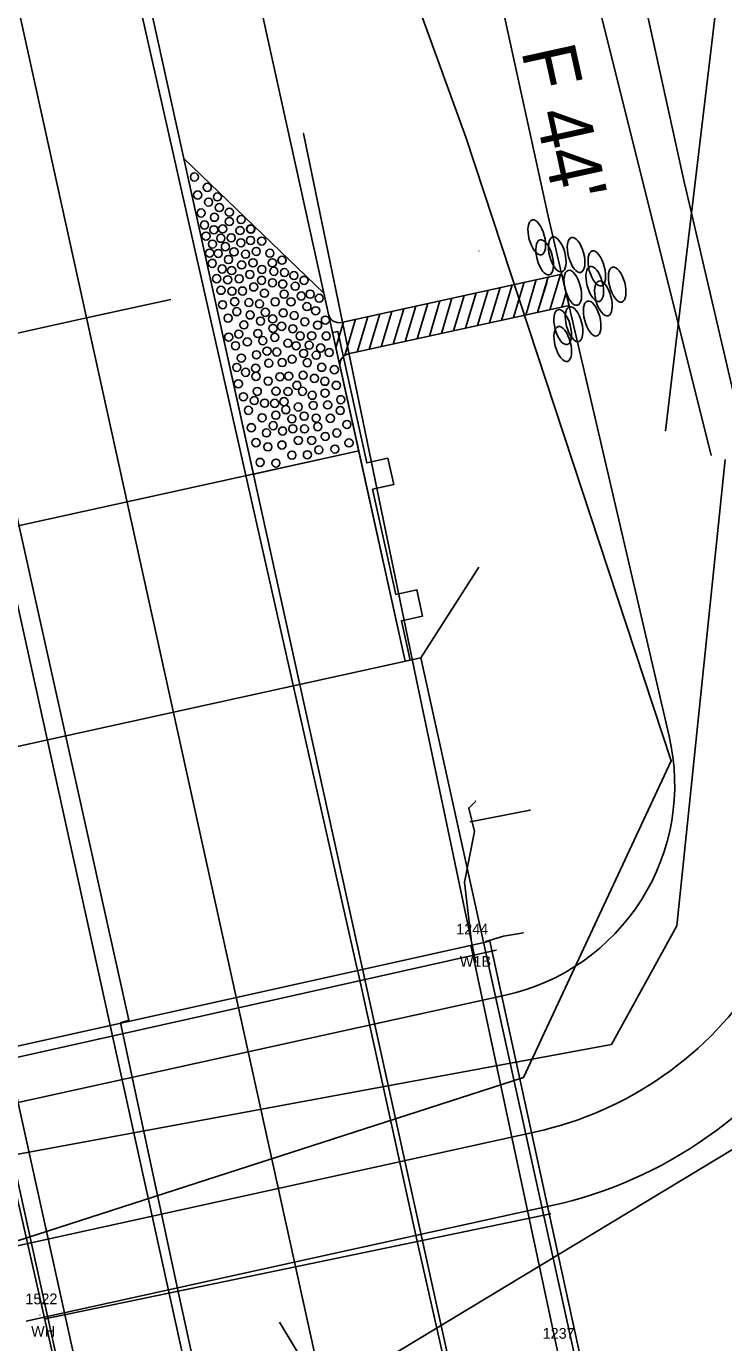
# Model space of a CAD drawing. Extents: x 2519952 to 2531965, y 848341 to 887632.
# Drawn here: x 2524242.1 to 2524306.9, y 857048.4 to 857170.6 of the extents above; entities that cross this region are included whole.
import ezdxf

# ---------------------------------------------------------------- set-up
doc = ezdxf.new("R2010")
doc.units = 0
for name, color, linetype in [('RD_EV_JW', 7, 'Continuous'), ('RD_EX_BldgApp', 7, 'Continuous'), ('RD_EX_BldgApp_txCode', 7, 'Continuous'), ('RD_EX_Bridge', 7, 'Continuous'), ('RD_EX_Conc', 7, 'Continuous'), ('RD_EX_DR_Pipe', 7, 'Continuous'), ('RD_EX_GuardRail', 7, 'Continuous'), ('RD_EX_H2O', 7, 'Continuous'), ('RD_EX_Misc', 7, 'Continuous'), ('RD_EX_Road', 7, 'Continuous'), ('RD_EX_VEG', 7, 'Continuous'), ('RD_HC_Cl', 7, 'Continuous'), ('RD_HC_Data_Tic', 7, 'Continuous'), ('RD_PD_BCA', 7, 'Continuous'), ('RD_PD_Bridge', 7, 'Continuous'), ('RD_PD_CstnLmt', 7, 'Continuous'), ('RD_PD_DR_ErosCtrl', 7, 'Continuous'), ('RD_PD_Final_TrvlWay', 7, 'Continuous'), ('RD_PD_GR', 7, 'Continuous'), ('RD_PD_PaveShd', 7, 'Continuous'), ('RD_PD_TX_CstnLmt', 7, 'Continuous'), ('RD_SMD_Locator', 7, 'Continuous')]:
    doc.layers.add(name, color=color, linetype=linetype)

# ---------------------------------------------------------------- blocks, each defined once
blk = doc.blocks.new('TBC1')
at = {"layer": 'RD_PD_GR'}
blk.add_lwpolyline([(12.5, 2.5), (15, 2.5), (15, 0.49), (25, 0.49), (25, 2.5), (27.5, 2.5), (27.5, 0.49), (31.25, 0.49), (31.25, 0), (0, 0), (0, 0.49), (12.5, 0.49)], close=True, dxfattribs=at)

msp = doc.modelspace()

# ---------------------------------------------------------------- linework, layer by layer
at = {"layer": 'RD_EV_JW'}
msp.add_lwpolyline([(2524241.25, 857057.8), (2524288.29, 857072.98), (2524302, 857102.41), (2524282.93, 857160.32), (2524257.89, 857229.33), (2524228.28, 857368.09), (2524210.76, 857440.65), (2524188.72, 857541.07), (2524178.8, 857585.79), (2524207.91, 857589.59), (2524237.38, 857595.52)], dxfattribs=at)
at = {"layer": 'RD_EX_BldgApp'}
for points in [[(2524299.52, 857011.21), (2524291.4, 857047.73), (2524283.39, 857085.27)], [(2524256.76, 857001.69), (2524248.36, 857039.08), (2524240.29, 857075.67)]]:
    msp.add_lwpolyline(points, dxfattribs=at)
at = {"layer": 'RD_EX_Bridge'}
for points in [[(2524288.28, 857086.43), (2524286.42, 857086.12), (2524284.79, 857085.63)], [(2524254.99, 857001.37), (2524301.28, 857011.6), (2524285.15, 857085.66), (2524238.23, 857075.21), (2524254.99, 857001.37)]]:
    msp.add_lwpolyline(points, dxfattribs=at)
at = {"layer": 'RD_EX_Conc'}
msp.add_lwpolyline([(2524283.42, 857085.84), (2524282.82, 857091.13), (2524283.73, 857095.82), (2524283.2, 857098.01), (2524283.85, 857098.66)], dxfattribs=at)
at = {"layer": 'RD_EX_DR_Pipe'}
msp.add_line((2524283.35, 857096.74), (2524288.89, 857097.83), dxfattribs=at)
at = {"layer": 'RD_EX_GuardRail'}
msp.add_lwpolyline([(2524283.87, 857083.68), (2524278.32, 857110.03), (2524267.88, 857160.66)], dxfattribs=at)
at = {"layer": 'RD_EX_H2O'}
msp.add_lwpolyline([(2524218.99, 857071.27), (2524223.78, 857062.61), (2524296.44, 857076.06), (2524302.51, 857087.07), (2524307.01, 857130.38)], dxfattribs=at)
at = {"layer": 'RD_EX_Misc'}
for p, q in [((2524238.53, 857074.24), (2524285.74, 857084.83)), ((2524290.8, 857060.34), (2524243.91, 857050.57))]:
    msp.add_line(p, q, dxfattribs=at)
msp.add_lwpolyline([(2524546.39, 857089.12), (2524517.38, 857137.92), (2524538.03, 857176.84), (2524519.61, 857206.94), (2524513, 857216.34), (2524463.61, 857251.75), (2524420.32, 857237.04), (2524384.22, 857230.02), (2524354.94, 857196.44), (2524330.04, 857206.28), (2524307.73, 857185.7), (2524301.47, 857133.05)], dxfattribs=at)
at = {"layer": 'RD_EX_Road'}
for p, q in [((2524272.86, 857083.08), (2524251.32, 857178.56)), ((2524251.66, 857078.33), (2524230.4, 857173.95)), ((2524272.98, 857082.6), (2524272.86, 857083.08)), ((2524278.38, 857057.92), (2524272.98, 857082.6)), ((2524250.88, 857078.06), (2524251.66, 857078.33)), ((2524256.26, 857052.98), (2524250.88, 857078.06)), ((2524283.87, 857033.71), (2524278.38, 857057.92)), ((2524261.6, 857028.54), (2524256.26, 857052.98))]:
    msp.add_line(p, q, dxfattribs=at)
at = {"layer": 'RD_EX_VEG'}
msp.add_lwpolyline([(2524305.71, 857130.78), (2524291.95, 857185.88), (2524213.1, 857577.99), (2524167.19, 857800.01)], dxfattribs=at)
at = {"layer": 'RD_HC_Cl'}
for p, q in [((2524121.25, 857717.97), (2524677.84, 855190.33)), ((2524152.13, 856972.4), (2524317.26, 857072.09))]:
    msp.add_line(p, q, dxfattribs=at)
at = {"layer": 'RD_HC_Data_Tic'}
for p, q in [((2524247.74, 857143.53), (2524255.55, 857145.25)), ((2524247.74, 857143.53), (2524239.93, 857141.81)), ((2524269.78, 857043.43), (2524265.64, 857050.27))]:
    msp.add_line(p, q, dxfattribs=at)
at = {"layer": 'RD_PD_BCA'}
msp.add_lwpolyline([(2524242.14, 857050.37), (2524290.92, 857061.11)], dxfattribs=at)
msp.add_arc((2524282.32, 857100.17), 40, 282.4185, 13.0724, dxfattribs=at)
at = {"layer": 'RD_PD_Bridge'}
for p, q in [((2524230.02, 857121.71), (2524272.99, 857131.17)), ((2524277.29, 857111.64), (2524272.99, 857131.17)), ((2524278.76, 857111.96), (2524284.14, 857120.39))]:
    msp.add_line(p, q, dxfattribs=at)
for points in [[(2524278.76, 857111.96), (2524232.86, 857101.86)], [(2524306.71, 856985.01), (2524278.76, 857111.96)], [(2524232.86, 857101.86), (2524260.81, 856974.9)]]:
    msp.add_lwpolyline(points, dxfattribs=at)
at = {"layer": 'RD_PD_CstnLmt'}
for p, q in [((2524269.22, 857250.66), (2524290.59, 857152.97)), ((2524290.59, 857152.97), (2524301.8, 857104.7))]:
    msp.add_line(p, q, dxfattribs=at)
msp.add_lwpolyline([(2524237.84, 857069.9), (2524286.62, 857080.64)], dxfattribs=at)
msp.add_arc((2524282.32, 857100.17), 20, 282.4185, 13.0724, dxfattribs=at)
at = {"layer": 'RD_PD_DR_ErosCtrl'}
for p, q in [((2524281.92, 857253.43), (2524303.29, 857155.74)), ((2524303.26, 857155.91), (2524314.47, 857107.64))]:
    msp.add_line(p, q, dxfattribs=at)
msp.add_lwpolyline([(2524240.63, 857057.2), (2524289.42, 857067.94)], dxfattribs=at)
msp.add_arc((2524282.32, 857100.17), 33, 282.4185, 13.0724, dxfattribs=at)
at = {"layer": 'RD_PD_Final_TrvlWay'}
for p, q in [((2524221.83, 857317.02), (2524496.02, 856071.85)), ((2524198.39, 857311.86), (2524472.58, 856066.69))]:
    msp.add_line(p, q, dxfattribs=at)
at = {"layer": 'RD_PD_GR'}
msp.add_line((2524222.18, 857361.9), (2524270.57, 857142.16), dxfattribs=at)
at = {"layer": 'RD_PD_PaveShd'}
for p, q in [((2524256.77, 857158.32), (2524269.76, 857145.82)), ((2524263.22, 857129.02), (2524256.77, 857158.32)), ((2524271.39, 857143.11), (2524291.84, 857147.6)), ((2524289.6, 857144.04), (2524290.59, 857147.33)), ((2524290.72, 857144.28), (2524291.71, 857147.57)), ((2524290.72, 857144.28), (2524291.71, 857147.57)), ((2524291.84, 857147.6), (2524292.52, 857144.68)), ((2524284.02, 857142.81), (2524285, 857146.1)), ((2524284.02, 857142.81), (2524285, 857146.1)), ((2524285.14, 857143.06), (2524286.12, 857146.34)), ((2524285.14, 857143.06), (2524286.12, 857146.34)), ((2524286.25, 857143.3), (2524287.24, 857146.59)), ((2524286.25, 857143.3), (2524287.12, 857146.18)), ((2524287.37, 857143.55), (2524288.35, 857146.83)), ((2524287.37, 857143.55), (2524288.35, 857146.83)), ((2524288.49, 857143.79), (2524289.47, 857147.08)), ((2524288.49, 857143.79), (2524289.47, 857147.08)), ((2524289.6, 857144.04), (2524290.47, 857146.92)), ((2524270.41, 857142.89), (2524269.76, 857145.82)), ((2524278.43, 857141.58), (2524279.42, 857144.87)), ((2524278.43, 857141.58), (2524279.42, 857144.87)), ((2524279.55, 857141.83), (2524280.53, 857145.12)), ((2524279.55, 857141.83), (2524280.53, 857145.12)), ((2524280.67, 857142.07), (2524281.65, 857145.36)), ((2524280.67, 857142.07), (2524281.65, 857145.36)), ((2524281.78, 857142.32), (2524282.77, 857145.61)), ((2524281.78, 857142.32), (2524282.77, 857145.61)), ((2524282.9, 857142.56), (2524283.88, 857145.85)), ((2524282.9, 857142.56), (2524283.88, 857145.85)), ((2524291.84, 857144.53), (2524292.24, 857145.87)), ((2524291.84, 857144.53), (2524292.24, 857145.87)), ((2524292.52, 857144.68), (2524272.03, 857140.18)), ((2524272.84, 857140.36), (2524273.83, 857143.64)), ((2524272.84, 857140.36), (2524273.83, 857143.64)), ((2524273.96, 857140.6), (2524274.95, 857143.89)), ((2524273.96, 857140.6), (2524274.95, 857143.89)), ((2524275.08, 857140.85), (2524276.06, 857144.13)), ((2524275.08, 857140.85), (2524276.06, 857144.13)), ((2524276.2, 857141.09), (2524277.18, 857144.38)), ((2524277.31, 857141.34), (2524278.3, 857144.63)), ((2524277.31, 857141.34), (2524278.3, 857144.63)), ((2524271.05, 857139.96), (2524270.41, 857142.89)), ((2524270.88, 857140.76), (2524271.59, 857143.15)), ((2524271.71, 857140.04), (2524272.71, 857143.4)), ((2524272.99, 857131.17), (2524271.05, 857139.96)), ((2524263.22, 857129.02), (2524272.99, 857131.17))]:
    msp.add_line(p, q, dxfattribs=at)
for centre in [(2524257.75, 857156.61), (2524258.94, 857155.65), (2524258.94, 857155.65), (2524258.05, 857154.94), (2524258.05, 857154.94), (2524259.06, 857154.28), (2524259.06, 857154.28), (2524259.88, 857154.76), (2524259.88, 857154.76), (2524258.37, 857153.27), (2524258.37, 857153.27), (2524260.06, 857153.77), (2524260.06, 857153.77), (2524260.99, 857153.34), (2524258.68, 857152.15), (2524258.68, 857152.15), (2524259.55, 857151.71), (2524259.55, 857151.71), (2524259.6, 857152.87), (2524259.6, 857152.87), (2524260.37, 857151.79), (2524260.37, 857151.79), (2524260.99, 857152.47), (2524260.99, 857152.47), (2524262.08, 857152.66), (2524262.08, 857152.66), (2524262.96, 857151.79), (2524262.98, 857151.77), (2524258.82, 857151.12), (2524258.82, 857151.12), (2524260.2, 857150.92), (2524260.2, 857150.92), (2524261.16, 857150.96), (2524261.16, 857150.96), (2524261.98, 857151.64), (2524261.98, 857151.64), (2524262.06, 857150.5), (2524262.06, 857150.5), (2524262.95, 857150.72), (2524262.95, 857150.72), (2524263.99, 857150.66), (2524263.99, 857150.66), (2524259.16, 857149.54), (2524259.16, 857149.54), (2524259.42, 857150.38), (2524259.42, 857150.38), (2524259.96, 857149.51), (2524259.96, 857149.51), (2524260.62, 857150.14), (2524260.62, 857150.14), (2524261.42, 857149.66), (2524261.42, 857149.66), (2524262.49, 857149.44), (2524262.49, 857149.44), (2524263.48, 857149.7), (2524263.48, 857149.7), (2524264.75, 857149.53), (2524264.75, 857149.53), (2524259.4, 857148.59), (2524259.4, 857148.59), (2524260.32, 857148.07), (2524260.32, 857148.07), (2524260.91, 857148.95), (2524260.91, 857148.95), (2524262.13, 857148.45), (2524262.13, 857148.45), (2524263.18, 857148.64), (2524263.18, 857148.64), (2524264.01, 857148.02), (2524264.01, 857148.02), (2524264.98, 857148.64), (2524264.98, 857148.64), (2524265.87, 857148.88), (2524265.88, 857148.88), (2524259.81, 857147.17), (2524259.81, 857147.17), (2524260.83, 857147.07), (2524260.83, 857147.07), (2524261.2, 857147.92), (2524261.2, 857147.92), (2524261.9, 857147.16), (2524261.9, 857147.16), (2524262.89, 857147.56), (2524262.89, 857147.56), (2524263.98, 857147.01), (2524263.98, 857147.01), (2524264.99, 857146.79), (2524264.99, 857146.79), (2524265.12, 857147.85), (2524265.12, 857147.85), (2524266.1, 857147.74), (2524266.1, 857147.74), (2524266.98, 857147.46), (2524266.98, 857147.46), (2524267.92, 857147.01), (2524267.92, 857147.01), (2524260.21, 857146.09), (2524260.21, 857146.09), (2524261.23, 857146), (2524261.23, 857146), (2524262.21, 857146.02), (2524262.21, 857146.02), (2524263.25, 857146.4), (2524263.25, 857146.4), (2524264.24, 857145.82), (2524264.24, 857145.82), (2524265.94, 857146.67), (2524265.94, 857146.67), (2524266.07, 857145.73), (2524266.07, 857145.73), (2524267.1, 857146.47), (2524267.1, 857146.47), (2524267.66, 857145.56), (2524267.66, 857145.56), (2524268.49, 857145.73), (2524268.49, 857145.73), (2524260.36, 857144.75), (2524260.36, 857144.75), (2524261.48, 857145.03), (2524261.48, 857145.03), (2524262.8, 857144.95), (2524262.8, 857144.95), (2524263.78, 857144.83), (2524263.78, 857144.83), (2524265.24, 857145.02), (2524265.24, 857145.02), (2524266.71, 857145.02), (2524266.71, 857145.02), (2524268.19, 857144.58), (2524268.19, 857144.58), (2524269.33, 857145.35), (2524269.33, 857145.35), (2524269.33, 857145.35), (2524260.87, 857143.5), (2524260.87, 857143.5), (2524261.68, 857144.11), (2524261.68, 857144.11), (2524262.91, 857143.8), (2524262.91, 857143.8), (2524263.88, 857143.23), (2524263.88, 857143.23), (2524264.33, 857144.04), (2524264.33, 857144.04), (2524265.01, 857143.43), (2524265.01, 857143.43), (2524265.99, 857143.99), (2524265.99, 857143.99), (2524267.01, 857143.74), (2524267.01, 857143.74), (2524267.99, 857143.17), (2524267.99, 857143.17), (2524269, 857144.19), (2524269, 857144.19), (2524269.9, 857143.32), (2524269.9, 857143.32), (2524261.86, 857142.02), (2524261.86, 857142.02), (2524262.34, 857142.88), (2524262.34, 857142.88), (2524263.64, 857142.08), (2524263.64, 857142.08), (2524265.04, 857142.55), (2524265.04, 857142.55), (2524265.84, 857142.74), (2524265.84, 857142.74), (2524266.87, 857142.52), (2524266.87, 857142.52), (2524269.18, 857142.85), (2524269.18, 857142.85), (2524260.93, 857141.74), (2524260.93, 857141.74), (2524261.56, 857140.94), (2524261.56, 857140.94), (2524262.66, 857141.3), (2524262.66, 857141.3), (2524264.09, 857141.41), (2524264.09, 857141.41), (2524265.2, 857141.72), (2524265.2, 857141.72), (2524266.42, 857141.17), (2524266.42, 857141.17), (2524267.18, 857140.94), (2524267.18, 857140.94), (2524267.56, 857141.85), (2524267.56, 857141.85), (2524268.39, 857140.99), (2524268.39, 857140.99), (2524268.63, 857141.86), (2524268.63, 857141.86), (2524269.46, 857140.73), (2524269.46, 857140.73), (2524269.98, 857141.85), (2524269.98, 857141.85), (2524262.1, 857139.79), (2524262.1, 857139.79), (2524263.5, 857140.1), (2524263.5, 857140.1), (2524264.48, 857140.44), (2524264.48, 857140.44), (2524265.39, 857140.36), (2524265.39, 857140.36), (2524266.81, 857139.69), (2524266.81, 857139.69), (2524267.88, 857140.23), (2524267.88, 857140.23), (2524269.05, 857140.06), (2524269.05, 857140.06), (2524270.26, 857140.31), (2524270.26, 857140.31), (2524261.68, 857138.93), (2524262.49, 857138.47), (2524262.49, 857138.47), (2524263.43, 857138.85), (2524263.43, 857138.85), (2524264.65, 857139.32), (2524264.65, 857139.32), (2524265.89, 857139.38), (2524265.89, 857139.38), (2524268.22, 857139.37), (2524268.22, 857139.37), (2524269.56, 857138.94), (2524269.56, 857138.94), (2524270.73, 857138.72), (2524270.73, 857138.72), (2524261.82, 857137.41), (2524261.82, 857137.41), (2524263.46, 857138.1), (2524263.46, 857138.1), (2524264.59, 857137.66), (2524264.59, 857137.66), (2524265.68, 857138.06), (2524265.68, 857138.06), (2524266.5, 857138.12), (2524266.5, 857138.12), (2524267.26, 857137.26), (2524267.26, 857137.26), (2524267.83, 857138.2), (2524267.83, 857138.2), (2524268.88, 857137.91), (2524268.88, 857137.91), (2524269.85, 857137.64), (2524269.85, 857137.64), (2524270.92, 857137.26), (2524270.92, 857137.26), (2524262.29, 857136.2), (2524262.29, 857136.2), (2524263.3, 857135.85), (2524263.3, 857135.85), (2524263.58, 857136.7), (2524263.58, 857136.7), (2524265.32, 857136.72), (2524265.32, 857136.72), (2524266.43, 857136.69), (2524266.43, 857136.69), (2524267.77, 857136.71), (2524267.77, 857136.71), (2524268.68, 857136.34), (2524268.68, 857136.34), (2524269.87, 857136.54), (2524269.87, 857136.54), (2524271.33, 857135.93), (2524271.33, 857135.93), (2524262.76, 857134.94), (2524262.76, 857134.94), (2524264.26, 857135.61), (2524264.26, 857135.61), (2524265.19, 857135.59), (2524265.19, 857135.59), (2524266.06, 857135.75), (2524266.06, 857135.75), (2524266.23, 857135.01), (2524267.38, 857135.25), (2524267.38, 857135.25), (2524268.77, 857135.4), (2524268.77, 857135.4), (2524270.11, 857135.45), (2524270.11, 857135.45), (2524271.28, 857134.92), (2524271.28, 857134.92), (2524263.03, 857133.33), (2524263.03, 857133.33), (2524264.03, 857134.25), (2524264.03, 857134.25), (2524265.06, 857133.52), (2524265.06, 857133.52), (2524265.3, 857134.49), (2524265.3, 857134.49), (2524266.79, 857134.15), (2524266.79, 857134.15), (2524267.93, 857134.4), (2524267.93, 857134.4), (2524269.04, 857134.22), (2524269.04, 857134.22), (2524269.19, 857133.43), (2524269.19, 857133.43), (2524270.36, 857134.2), (2524270.36, 857134.2), (2524271.9, 857133.63), (2524271.9, 857133.63), (2524264.43, 857132.85), (2524264.43, 857132.85), (2524265.93, 857133.02), (2524265.93, 857133.02), (2524266.88, 857133.23), (2524266.88, 857133.23), (2524267.39, 857132.15), (2524267.39, 857132.15), (2524267.96, 857133.22), (2524267.96, 857133.22), (2524268.63, 857132.15), (2524268.63, 857132.15), (2524269.89, 857132.52), (2524269.89, 857132.52), (2524270.96, 857132.84), (2524270.96, 857132.84), (2524263.46, 857131.94), (2524263.46, 857131.94), (2524264.56, 857131.55), (2524264.56, 857131.55), (2524265.87, 857131.72), (2524265.87, 857131.72), (2524269.29, 857131.27), (2524269.29, 857131.27), (2524270.78, 857131.34), (2524270.78, 857131.34), (2524272.09, 857131.92), (2524272.09, 857131.92), (2524272.09, 857131.92), (2524263.84, 857130.11), (2524263.84, 857130.11), (2524265.31, 857130.04), (2524265.31, 857130.04), (2524266.79, 857130.78), (2524266.79, 857130.78), (2524268.23, 857130.82), (2524268.23, 857130.82)]:
    msp.add_circle(centre, 0.375, dxfattribs=at)
for centre, start, end in [((2524271.17, 857144.08), 192.4185, 282.3889), ((2524272.25, 857139.2), 102.3889, 192.4185)]:
    msp.add_arc(centre, 1, start, end, dxfattribs=at)
for centre in [(2524289.52, 857151), (2524290.25, 857149.15), (2524291.42, 857149.42), (2524291.42, 857149.42), (2524293.17, 857149.37), (2524293.17, 857149.37), (2524295.09, 857148.12), (2524295.09, 857148.12), (2524294.9, 857146.68), (2524294.9, 857146.68), (2524292.86, 857146.32), (2524292.86, 857146.32), (2524296.98, 857146.62), (2524296.98, 857146.62), (2524295.7, 857145.33), (2524295.7, 857145.33), (2524294.66, 857143.47), (2524294.66, 857143.47), (2524291.92, 857142.67), (2524291.92, 857142.67), (2524292.98, 857142.94), (2524292.98, 857142.94), (2524291.93, 857141.1), (2524291.93, 857141.1)]:
    msp.add_ellipse(centre, major_axis=(-0.43, 1.62), ratio=0.429445, dxfattribs=at)
at = {"layer": 'RD_SMD_Locator'}
for centre in [(2524267.88, 857160.66), (2524282.93, 857160.32), (2524284.15, 857149.73), (2524301.47, 857133.05), (2524305.71, 857130.78), (2524278.32, 857110.03), (2524302, 857102.41), (2524283.85, 857098.66), (2524283.2, 857098.01), (2524288.89, 857097.83), (2524283.35, 857096.74), (2524283.73, 857095.82), (2524282.82, 857091.13), (2524286.42, 857086.12), (2524288.28, 857086.43), (2524302.51, 857087.07), (2524283.39, 857085.27), (2524283.42, 857085.84), (2524284.79, 857085.63), (2524285.15, 857085.66), (2524285.74, 857084.83), (2524283.87, 857083.68), (2524272.86, 857083.08), (2524272.98, 857082.6), (2524250.88, 857078.06), (2524251.66, 857078.33), (2524296.44, 857076.06), (2524288.29, 857072.98), (2524290.8, 857060.34), (2524278.38, 857057.92), (2524256.26, 857052.98), (2524243.41, 857050.93), (2524243.91, 857050.57)]:
    msp.add_circle(centre, 0.001, dxfattribs=at)

# ---------------------------------------------------------------- block references
at = {"layer": 'RD_PD_Bridge', "rotation": -77.58151740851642}
msp.add_blockref('TBC1', (2524270.57, 857142.16), dxfattribs=at)

# ---------------------------------------------------------------- texts
at = {"layer": 'RD_EX_BldgApp_txCode'}
for s, p in [('1244', (2524282.04, 857086.27)), ('W1B', (2524282.38, 857083.27)), ('1522', (2524242.06, 857051.93)), ('WH', (2524242.59, 857048.93)), ('1237', (2524290.06, 857048.73))]:
    msp.add_text(s, height=1, dxfattribs=at).set_placement(p)
at = {"layer": 'RD_PD_TX_CstnLmt'}
msp.add_text("F 44'", height=5, rotation=282.4185, dxfattribs=at).set_placement((2524288.06, 857168.33))

doc.saveas('drawing.dxf')
